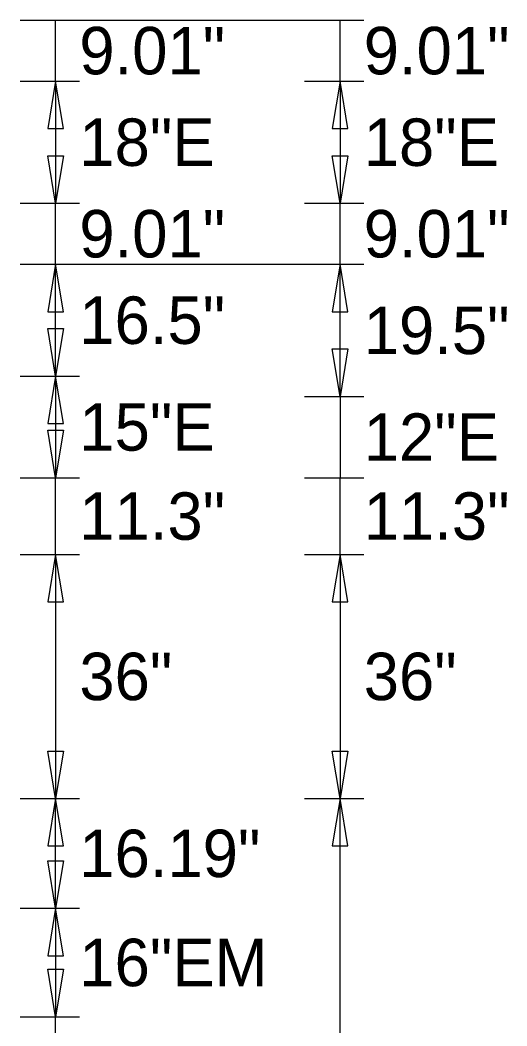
# Model space of a CAD drawing. Extents: x 2149934 to 2150188, y 145114 to 145238.
# Drawn here: x 2150106.51 to 2150112.5, y 145154.85 to 145167.22 of the extents above; entities that cross this region are included whole.
import ezdxf

# ---------------------------------------------------------------- set-up
doc = ezdxf.new("R2010")
doc.units = 0
doc.layers.add('GSDIMS', color=7, linetype='Continuous')

msp = doc.modelspace()

# ---------------------------------------------------------------- linework, layer by layer
at = {"layer": 'GSDIMS'}
for p, q in [((2150106.508, 145167.217), (2150107.237, 145167.217)), ((2150106.508, 145167.217), (2150110.008, 145167.217)), ((2150106.945, 145166.467), (2150106.945, 145167.217)), ((2150110.008, 145167.217), (2150110.737, 145167.217)), ((2150110.445, 145166.467), (2150110.445, 145167.217)), ((2150106.508, 145166.467), (2150107.237, 145166.467)), ((2150106.508, 145166.467), (2150107.237, 145166.467)), ((2150106.945, 145166.467), (2150106.945, 145164.967)), ((2150110.008, 145166.467), (2150110.737, 145166.467)), ((2150110.008, 145166.467), (2150110.737, 145166.467)), ((2150110.445, 145166.467), (2150110.445, 145164.967)), ((2150106.508, 145164.967), (2150107.237, 145164.967)), ((2150106.508, 145164.967), (2150107.237, 145164.967)), ((2150106.945, 145164.216), (2150106.945, 145164.967)), ((2150110.008, 145164.967), (2150110.737, 145164.967)), ((2150110.008, 145164.967), (2150110.737, 145164.967)), ((2150110.445, 145164.216), (2150110.445, 145164.967)), ((2150106.508, 145164.216), (2150107.237, 145164.216)), ((2150106.508, 145164.216), (2150110.008, 145164.216)), ((2150106.508, 145164.216), (2150107.237, 145164.216)), ((2150106.508, 145164.216), (2150110.008, 145164.216)), ((2150106.945, 145162.841), (2150106.945, 145164.216)), ((2150110.008, 145164.216), (2150110.737, 145164.216)), ((2150110.008, 145164.216), (2150110.737, 145164.216)), ((2150110.445, 145162.591), (2150110.445, 145164.216)), ((2150106.508, 145162.841), (2150107.237, 145162.841)), ((2150106.508, 145162.841), (2150107.237, 145162.841)), ((2150106.945, 145162.841), (2150106.945, 145161.591)), ((2150110.008, 145162.591), (2150110.737, 145162.591)), ((2150110.008, 145162.591), (2150110.737, 145162.591)), ((2150110.445, 145162.591), (2150110.445, 145161.591)), ((2150106.508, 145161.591), (2150107.237, 145161.591)), ((2150106.508, 145161.591), (2150107.237, 145161.591)), ((2150106.945, 145160.65), (2150106.945, 145161.591)), ((2150110.008, 145161.591), (2150110.737, 145161.591)), ((2150110.008, 145161.591), (2150110.737, 145161.591)), ((2150110.445, 145160.65), (2150110.445, 145161.591)), ((2150106.508, 145160.65), (2150107.237, 145160.65)), ((2150106.508, 145160.65), (2150107.237, 145160.65)), ((2150106.945, 145160.65), (2150106.945, 145157.65)), ((2150110.008, 145160.65), (2150110.737, 145160.65)), ((2150110.008, 145160.65), (2150110.737, 145160.65)), ((2150110.445, 145160.65), (2150110.445, 145157.65)), ((2150106.508, 145157.65), (2150107.237, 145157.65)), ((2150106.508, 145157.65), (2150107.237, 145157.65)), ((2150106.945, 145156.3), (2150106.945, 145157.65)), ((2150110.008, 145157.65), (2150110.737, 145157.65)), ((2150110.008, 145157.65), (2150110.737, 145157.65)), ((2150110.445, 145150.3), (2150110.445, 145157.65)), ((2150106.508, 145156.3), (2150107.237, 145156.3)), ((2150106.508, 145156.3), (2150107.237, 145156.3)), ((2150106.945, 145156.3), (2150106.945, 145154.967)), ((2150106.508, 145154.967), (2150107.237, 145154.967)), ((2150106.508, 145154.967), (2150107.237, 145154.967)), ((2150106.945, 145153.967), (2150106.945, 145154.967))]:
    msp.add_line(p, q, dxfattribs=at)
for points in [[(2150106.945, 145166.467), (2150106.848, 145165.884), (2150107.043, 145165.884)], [(2150110.445, 145166.467), (2150110.348, 145165.884), (2150110.543, 145165.884)], [(2150106.945, 145164.967), (2150106.848, 145165.55), (2150107.043, 145165.55)], [(2150110.445, 145164.967), (2150110.348, 145165.55), (2150110.543, 145165.55)], [(2150106.945, 145164.216), (2150106.848, 145163.633), (2150107.043, 145163.633)], [(2150110.445, 145164.216), (2150110.348, 145163.633), (2150110.543, 145163.633)], [(2150106.945, 145162.841), (2150106.848, 145163.425), (2150107.043, 145163.425)], [(2150110.445, 145162.591), (2150110.348, 145163.175), (2150110.543, 145163.175)], [(2150106.945, 145162.841), (2150106.848, 145162.258), (2150107.043, 145162.258)], [(2150106.945, 145161.591), (2150106.848, 145162.175), (2150107.043, 145162.175)], [(2150106.945, 145160.65), (2150106.848, 145160.066), (2150107.043, 145160.066)], [(2150110.445, 145160.65), (2150110.348, 145160.066), (2150110.543, 145160.066)], [(2150106.945, 145157.65), (2150106.848, 145158.233), (2150107.043, 145158.233)], [(2150110.445, 145157.65), (2150110.348, 145158.233), (2150110.543, 145158.233)], [(2150106.945, 145157.65), (2150106.848, 145157.066), (2150107.043, 145157.066)], [(2150110.445, 145157.65), (2150110.348, 145157.066), (2150110.543, 145157.066)], [(2150106.945, 145156.3), (2150106.848, 145156.884), (2150107.043, 145156.884)], [(2150106.945, 145156.3), (2150106.848, 145155.717), (2150107.043, 145155.717)], [(2150106.945, 145154.967), (2150106.848, 145155.55), (2150107.043, 145155.55)]]:
    msp.add_lwpolyline(points, close=True, dxfattribs=at)

# ---------------------------------------------------------------- texts
for s, p in [('9.01"', (2150107.237, 145166.551)), ('9.01"', (2150110.737, 145166.551)), ('18"E', (2150107.237, 145165.425)), ('18"E', (2150110.737, 145165.425)), ('9.01"', (2150107.237, 145164.3)), ('9.01"', (2150110.737, 145164.3)), ('16.5"', (2150107.237, 145163.237)), ('19.5"', (2150110.737, 145163.112)), ('15"E', (2150107.237, 145161.925)), ('12"E', (2150110.737, 145161.8)), ('11.3"', (2150107.237, 145160.829)), ('11.3"', (2150110.737, 145160.829)), ('36"', (2150107.237, 145158.858)), ('36"', (2150110.737, 145158.858)), ('16.19"', (2150107.237, 145156.683)), ('16"EM', (2150107.237, 145155.342))]:
    msp.add_text(s, height=0.5833, dxfattribs=at).set_placement(p)

doc.saveas('drawing.dxf')
